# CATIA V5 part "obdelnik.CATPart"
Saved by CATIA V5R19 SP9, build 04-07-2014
Part number: Part3
Bounding box of the stored display mesh (mm): x 0 to 0, y 0 to 50, z 0 to 10
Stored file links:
  W:\obdelnik.CATPart
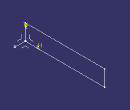
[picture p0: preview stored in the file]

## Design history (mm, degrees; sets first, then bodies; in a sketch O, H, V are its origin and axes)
Parameters
  group "Vstupní délky"
    a = 10 mm
    b = 50 mm
  group "Výpočet"
    uhlopricka_ze_vzorce = 50.9902 mm {= sqrt(a **2+b **2)}
  group "Výpočet.1"
    uhlopricka_z_geometrie = 50.9902 mm {= Sketch1.length(L5)}
AxisSystem1: origin (0, 0, 0), X (1, 0, 0), Y (0, 1, 0), Z (0, 0, 1)
Body1 (main body)
  Sketch1 on yz-plane, origin (0, 0, 0), H (0, 1, 0), V (0, 0, 1)
    line L1 (0, 0) -> (50, 0)
    line L2 (50, 0) -> (50, 10)
    line L3 (50, 10) -> (0, 10)
    line L4 (0, 10) -> (0, 0)
    construction line L5 (0, 0) -> (50, 10)
    length L4 = 10 {= a}
    length L3 = 50 {= b}
    length L5 = 50.9902 (reference)
    horizontal: L1 H, L3 H
    vertical: L2 V, L4 V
